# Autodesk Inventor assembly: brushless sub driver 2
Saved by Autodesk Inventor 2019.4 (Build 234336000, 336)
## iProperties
Created: 2021-02
Part Number: brushless sub driver 2
Document SubType Name: Assembly
Designer: Administrator
Title: brushless sub driver 2 v1
Author: Administrator
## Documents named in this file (3)
- c:\worker\convert-fusion-r01\tmp\job-1\28\output\files\da425021-f5ae-4251-bf5a-5edd51761a99\5602d32e-daf0-49d5-a714-cd7af2dbccd5.zip.iam
- c:\worker\convert-fusion-r01\tmp\job-1\28\output\files\da425021-f5ae-4251-bf5a-5edd51761a99\Board.ipt
- c:\worker\convert-fusion-r01\tmp\job-1\28\output\files\da425021-f5ae-4251-bf5a-5edd51761a99\Packages.iam
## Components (2 placed, 2 different names)
1. Board:1
2. Packages:1 [sub-assembly]
